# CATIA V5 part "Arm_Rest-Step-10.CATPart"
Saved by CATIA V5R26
Part number: Arm_Rest
Bounding box of the stored display mesh (mm): x 746.599 to 1432.298, y -782.976 to -630.25, z 345.981 to 524.952
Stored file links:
  D:\LinkedIn Learning\NURBS\CATIA\Class Parts\Arm_Rest-Step-11.CATPart
  D:\LinkedIn Learning\NURBS\Arm_Rest.CATPart
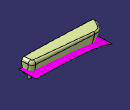
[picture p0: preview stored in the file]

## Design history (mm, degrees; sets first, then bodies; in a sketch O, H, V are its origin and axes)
AxisSystem1: origin (0, 0, 0), X (1, 0, 0), Y (0, 1, 0), Z (0, 0, 1)
StDynAnalysisRootNodeFeature1 "CATStDynAnalysisRootNodeName"
Set1 "REF DATA"
  CLDGeom1 "TOP"
  CLDGeom2 "FRONT"
  CLDGeom3 "AFT_BLEND"
  CLDGeom4 "END_AFT"
  CLDGeom5 "FORWARD_BLEND"
  CLDGeom6 "BOTTOM"
  CLDGeom7 "END_FORWARD"
  CLDGeom8 "UPPER_BLENDS"
  CLDGeom9 "LOWER_BLENDS"
  DatumSurface1 "DOOR_TRIM_SURFACE"
Set2 "FORM"
  Set3 "SLABS"
    DatumSurface2 to DatumSurface6
  Set4 "CURVES"
    St3DCurveFeature1 "CATSt3DCurveFeatureName": Order 6, CreationType 1, ClosureMode false, ConstructionPoints ({point type Coord, X 863.1168, Y 0, Z 551.1449}; {point type Coord, X 868.9503, Y 0, Z 330.43}), SymmetryMode false
    St3DCurveFeature2 "CATSt3DCurveFeatureName": Order 6, CreationType 1, ClosureMode false, ConstructionPoints ({point type Coord, X 1369.3867, Y 0, Z 551.9965}; {point type Coord, X 1358.4038, Y 0, Z 335.6826}), SymmetryMode false
    Intersect1: ToIntersect1 DatumSurface4, ToIntersect2 DatumSurface5
    Intersect2: ToIntersect1 DatumSurface6, ToIntersect2 DatumSurface4
    CurvePar1: Offset Intersect2, Support DatumSurface6, Offset2 0, Offset1 30
    CurvePar2: Offset Intersect1, Support DatumSurface5, Offset2 50, Offset1 20
    Project1: ToProject St3DCurveFeature1, Support DatumSurface4, Direction edge [YZ plane of AxisSystem1 | XY plane of AxisSystem1]
    Project2: ToProject St3DCurveFeature2, Support DatumSurface4, Direction edge [YZ plane of AxisSystem1 | XY plane of AxisSystem1]
    Project3: ToProject St3DCurveFeature2, Support StTopoTypeFeature3, Direction edge [YZ plane of AxisSystem1 | XY plane of AxisSystem1]
    Project4: ToProject St3DCurveFeature1, Support StTopoTypeFeature3, Direction edge [YZ plane of AxisSystem1 | XY plane of AxisSystem1]
    Intersect3: ToIntersect1 edge of StTopoTypeFeature1, ToIntersect2 CurvePar2
    Intersect4: ToIntersect1 edge of StTopoTypeFeature2, ToIntersect2 CurvePar1
    Project5: ToProject Intersect4, Support edge of StTopoTypeFeature2
    Project6: ToProject Intersect3, Support edge of StTopoTypeFeature1
    Line1: type PtPt, FirstPoint Intersect3, SecondPoint Project6, Support StTopoTypeFeature1
    Line2: type PtPt, FirstPoint Intersect4, SecondPoint Project5, Support StTopoTypeFeature2
    Curve1: Elements (Intersect4; vertex of Project3), Support Blend2
    Curve2: Elements (Project5; vertex of Project3), Support DatumSurface2
    Curve3: Elements (vertex of Project4; Intersect3), Support Blend1
    Curve4: Elements (vertex of Project4; Project6), Support DatumSurface2
  Set5 "BLENDS"
    Blend1: StartLimit {blendlimit Curve Project1, Support DatumSurface4, TensionValues 1.1}, EndLimit {blendlimit Curve CurvePar2, Support DatumSurface5, TensionValues 1}
    Blend2: StartLimit {blendlimit Curve CurvePar1, Support DatumSurface6, TensionValues 0.9}, EndLimit {blendlimit Curve Project2, Support DatumSurface4, TensionValues 0.8}
    StTopoTypeFeature1 "CATStTopoTypeFeatureName": Children 15
    StTopoTypeFeature2 "CATStTopoTypeFeatureName": Children 35
    StTopoTypeFeature3 "CATStTopoTypeFeatureName": nls://CATStFeaturesStartUpsNLS/TopoVarRadiCke 35, nls://CATStFeaturesStartUpsNLS/TopoVarRadiCke 15
    Loft1: Sections (Line2; Project3), StartSectionTangent StTopoTypeFeature2, EndSectionTangent StTopoTypeFeature3, Guides ({loftguide GuideCurve Curve1, GuideTangent Blend2}; {loftguide GuideCurve Curve2, GuideTangent DatumSurface2})
    Loft2: Sections (Project4; Line1), StartSectionTangent StTopoTypeFeature3, EndSectionTangent StTopoTypeFeature1, Guides ({loftguide GuideCurve Curve3, GuideTangent Blend1}; {loftguide GuideCurve Curve4, GuideTangent DatumSurface2})
  Set6 "SPLITS"
    Split1: ToCut DatumSurface4, Cutting (Project1; edge of StTopoTypeFeature3; Project2)
    Split2: ToCut Blend2, Cutting Curve1
    Split3: ToCut DatumSurface6, Cutting (CurvePar1; edge of StTopoTypeFeature2)
    Split4: ToCut Blend1, Cutting Curve3
    Split5: ToCut DatumSurface5, Cutting (CurvePar2; edge of StTopoTypeFeature1)
    Split6: ToCut StTopoTypeFeature1, Cutting Line1
    Split7: ToCut StTopoTypeFeature3, Cutting (Project4; Project3)
    Split8: ToCut StTopoTypeFeature2, Cutting Line2
    Split9: ToCut DatumSurface2, Cutting (edge of StTopoTypeFeature3; edge of StTopoTypeFeature2; Curve2; edge of StTopoTypeFeature1; Curve4)
  Join1: Elements (Split9; Loft1; Loft2; Split6; Split7; Split8; Split2; Split4; Split5; Split1; Split3)
Body1 (main body)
